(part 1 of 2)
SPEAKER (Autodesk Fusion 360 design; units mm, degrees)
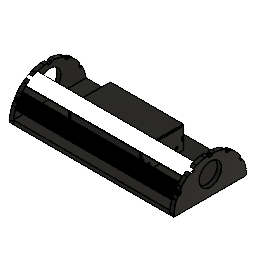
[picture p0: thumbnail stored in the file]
parameter "thickness" = 4
parameter "tabdepth" = 4
sketch "Sketch1" plane through (0, 0, 0) normal (0, 0, 1) x axis (1, 0, 0)
  line L1 (150, 0) -> (0, 0)
  line L2 (150, -70) -> (150, 0)
  line L3 (0, -70) -> (150, -70)
  line L4 (0, 0) -> (0, -70)
  point P1 (0, 0)
  point P2 (0, 0)
  point P3 (150, 0)
  point P5 (0, -70)
  horizontal L1
  vertical L2
  horizontal L3
  vertical L4
  coincident P1 P2
  dimension "d1" distance P2 P3 = 150
  dimension "d2" distance P2 P5 = 70
extrude "Extrude1" new body sketch "Sketch1" along normal blind 4
sketch "Sketch2" plane through (0, 0, 0) normal (-1, 0, 0) x axis (0, -1, 0)
  line L1 (70, 0) -> (0, 0)
  line L2 (70, 4) -> (70, 0)
  line L3 (0, 4) -> (70, 4)
  line L4 (0, 0) -> (0, 4)
  line L5 (60, 4) -> (10, 4)
  line L6 (60, 0) -> (60, 4)
  line L7 (10, 0) -> (60, 0)
  line L8 (10, 4) -> (10, 0)
  point P8 (60, 0)
  point P6 (10, 4)
  horizontal L5
  vertical L6
  horizontal L7
  vertical L8
  coincident L1 P8
  coincident L3 P6
  dimension "d7" distance L4 L8 = 10
  dimension "d8" distance L2 L6 = 10
extrude "Extrude2" add sketch "Sketch2" profile of L1 L3 L5 L6 L7 L8 along normal blind 4 (= "thickness")
sketch "Sketch3" plane through (150, 0, 0) normal (1, 0, 0) x axis (0, 1, 0)
  line L1 (0, 0) -> (-70, 0)
  line L2 (0, 4) -> (0, 0)
  line L3 (-70, 4) -> (0, 4)
  line L4 (-70, 0) -> (-70, 4)
  line L5 (-10, 4) -> (-60, 4)
  line L6 (-10, 0) -> (-10, 4)
  line L7 (-60, 0) -> (-10, 0)
  line L8 (-60, 4) -> (-60, 0)
  point P8 (-10, 0)
  point P10 (-10, 0)
  point P6 (-60, 4)
  horizontal L5
  vertical L6
  horizontal L7
  vertical L8
  coincident P8 P10
  coincident L3 P6
  dimension "d11" distance L4 L8 = 10
  dimension "d12" distance L2 L6 = 10
extrude "Extrude3" add sketch "Sketch3" profile of L1 L3 L5 L6 L7 L8 along normal blind 4 (= "thickness")
sketch "Sketch4" plane through (154, 0, 0) normal (1, 0, 0) x axis (0, 1, 0)
  line L1 (-10, 0) -> (-60, 0)
  line L2 (-10, 4) -> (-10, 0)
  line L3 (-60, 4) -> (-10, 4)
  line L4 (-60, 0) -> (-60, 4)
  line L5 (-70, 4) -> (-70, 0)
  line L6 (0, 0) -> (-70, 0)
  arc A1 centre (-35, 0) radius 35 clockwise from (-70, 0) to (0, 0)
  point P1 (0, 0)
  point P7 (0, 0)
  tangent A1 L5
  coincident P1 P7
  perpendicular L5 L6
extrude "Extrude4" new body sketch "Sketch4" profile of L2 L3 L4 A1 L6 no distance stored
extrude "Extrude5" of existing geometry no distance stored
sketch "Sketch5" plane through (150, 0, 0) normal (-1, 0, 0) x axis (0, -1, 0)
  line L1 (10, 0) -> (0, 0)
  line L2 (10, 4) -> (10, 0)
  line L3 (60, 4) -> (10, 4)
  line L4 (60, 0) -> (60, 4)
  line L5 (70, 0) -> (60, 0)
  arc A1 centre (35, 0) radius 35 clockwise from (0, 0) to (70, 0)
sketch "Sketch6" plane through (0, 0, 4) normal (0, 0, -1) x axis (1, 0, 0)
  line L1 (154, 60) -> (154, 10)
  line L2 (150, 60) -> (154, 60)
  line L3 (150, 10) -> (150, 60)
  line L4 (154, 10) -> (150, 10)
sketch "Sketch7" plane through (154, 0, 0) normal (1, 0, 0) x axis (0, 1, 0)
  line L1 (0, 0) -> (-10, 0)
  line L2 (-60, 0) -> (-70, 0)
  line L3 (-60, 4) -> (-60, 0)
  line L4 (-10, 4) -> (-60, 4)
  line L5 (-10, 0) -> (-10, 4)
  line L6 (-59.0789, 25.4009) -> (-63.6687, 20.0775)
  line L7 (-60.2396, 16.6833) -> (-63.6687, 20.0775)
  line L8 (-55.9565, 21.0105) -> (-60.2396, 16.6833)
  line L9 (-59.0789, 25.4009) -> (-55.9565, 21.0105)
  arc A1 centre (-35, 0) radius 35 clockwise from (-70, 0) to (0, 0)
  point P9 (-63.6687, 20.0775)
  point P10 (-59.0789, 25.4009)
  coincident A1 P9
  coincident A1 P10
  perpendicular L7 L8
sketch "Sketch9" plane through (154, 0, 0) normal (1, 0, 0) x axis (0, 1, 0)
  line L1 (0, 0) -> (-10, 0)
  line L2 (-60, 0) -> (-70, 0)
  line L3 (-60, 4) -> (-60, 0)
  line L4 (-10, 4) -> (-60, 4)
  line L5 (-10, 0) -> (-10, 4)
  line L6 (5.4969, 0) -> (-35, 0)
  line L7 (7.9535, 0) -> (-35, 0)
  line L8 (12.4131, 0) -> (-35, 0)
  horizontal L6
  horizontal L7
  horizontal L8
work_plane "WorkPlane3" AlongDistance -17.5
sketch "Sketch12" plane through (75, -35, 17.5) normal (0, 0, -1) x axis (1, 0, 0)
work_plane "WorkPlane4" AlongDistance -17.5
sketch "Sketch13" plane through (75, -35, 17.5) normal (0, 0, -1) x axis (1, 0, 0)
  line L1 (79, -35.0714) -> (79, 0)
  line L2 (75, -30.3109) -> (79, -30.3109)
  arc A1 centre (75, 0) radius 35 between (75, 35) and (75, -35)
  point P7 (79, -30.3109)
  point P8 (75, -30.3109)
  coincident L1 P7
  coincident A1 P8
work_plane "WorkPlane5" RotateAngle 60
sketch "Sketch27" plane through (154, 0, 0) normal (1, 0, 0) x axis (0, 1, 0)
  line L1 (0, 0) -> (-10, 0)
  line L2 (-60, 0) -> (-70, 0)
  line L3 (-60, 4) -> (-60, 0)
  line L4 (-10, 4) -> (-60, 4)
  line L5 (-10, 0) -> (-10, 4)
  arc A1 centre (-35, 0) radius 35 clockwise from (-70, 0) to (0, 0)
sketch "Sketch14" plane through (152, -4.6891, 17.5) normal (0, 0.866, 0.5) x axis (-1, 0, 0)
  line L1 (-2, 5) -> (-2, 0)
  line L2 (2, 5) -> (-2, 5)
  line L3 (2, -5) -> (2, 5)
  line L4 (-2, -5) -> (2, -5)
  line L5 (-2, 0) -> (-2, -5)
  point P2 (-2, 0)
  point P3 (-2, 0)
  point P4 (-2, 5)
  coincident P2 P3
  perpendicular L1 L2
  perpendicular L2 L3
  perpendicular L1 L4
  perpendicular L4 L5
  dimension "d34" distance P3 P4 = 5
extrude "Extrude8" cut sketch "Sketch14" against normal blind 4
sketch "Sketch15" plane through (75, -35, 17.5) normal (0, 0, -1) x axis (1, 0, 0)
  line L1 (79, 41.0609) -> (79, 0)
  line L2 (75, 30.3109) -> (79, 30.3109)
  arc A1 centre (79, 0) radius 35 between (79, -27.5) and (79, 35)
  point P7 (79, 30.3109)
  coincident A1 P7
  coincident L1 P7
work_plane "WorkPlane6" RotateAngle -60
sketch "Sketch16" plane through (152, -65.3109, 17.5) normal (0, -0.866, 0.5) x axis (-1, 0, 0)
  line L1 (2, -5) -> (2, 0)
  line L2 (-2, -5) -> (2, -5)
  line L3 (-2, 5) -> (-2, -5)
  line L4 (2, 5) -> (-2, 5)
  line L5 (2, 0) -> (2, 5)
  point P2 (2, 0)
  point P3 (2, 0)
  point P4 (2, -5)
  point P5 (-2, -5)
  point P6 (-2, 5)
  coincident P2 P3
  perpendicular L1 L2
  perpendicular L2 L3
  perpendicular L3 L4
  perpendicular L4 L5
  dimension "d39" distance P3 P4 = 5
  dimension "d40" distance P5 P6 = 10
extrude "Extrude9" cut sketch "Sketch16" against normal blind 4
work_plane "WorkPlane7" RotateAngle 0
sketch "Sketch17" plane through (152.9927, -35, 35) normal (0, 0, 1) x axis (1, 0, 0)
  line L1 (-3, 5) -> (-3, 0)
  line L2 (1, 5) -> (-3, 5)
  line L3 (1, -5) -> (1, 5)
  line L4 (-3, -5) -> (1, -5)
  line L5 (-3, 0) -> (-3, -5)
  vertical L1
  perpendicular L1 L2
  perpendicular L2 L3
  perpendicular L1 L4
  perpendicular L4 L5
extrude "Extrude10" cut sketch "Sketch17" against normal blind 4
work_plane "WorkPlane8" RotateAngle -7.5
sketch "Sketch18" plane through (150.7134, -52.7673, 30.155) normal (0, -0.5076, 0.8616) x axis (0, -0.8616, -0.5076)
  line L1 (-5, -0.75) -> (0, -0.75)
  line L2 (-5, 3.3553) -> (-5, -0.75)
  line L3 (5, 3.3553) -> (-5, 3.3553)
  line L4 (5, -0.75) -> (5, 3.3553)
  line L5 (0, -0.75) -> (5, -0.75)
  horizontal L1
  perpendicular L1 L2
  perpendicular L2 L3
  perpendicular L3 L4
  perpendicular L4 L5
extrude "Extrude11" cut sketch "Sketch18" against normal blind 4
extrude "Extrude12" cut of existing geometry blind -4
work_plane "WorkPlane9" RotateAngle 2.5
sketch "Sketch19" plane through (152.2402, -17.9965, 30.5922) normal (0, 0.4858, 0.8741) x axis (0, -0.8741, 0.4858)
  line L1 (5, 1.8) -> (0, 1.8)
  line L2 (5, -2.3) -> (5, 1.8)
  line L3 (-5, -2.3) -> (5, -2.3)
  line L4 (-5, 1.8) -> (-5, -2.3)
  line L5 (0, 1.8) -> (-5, 1.8)
  horizontal L1
  perpendicular L1 L2
  perpendicular L2 L3
  perpendicular L3 L4
  perpendicular L4 L5
extrude "Extrude13" cut sketch "Sketch19" against normal blind 4
sketch "Sketch20" plane through (154, 0, 0) normal (1, 0, 0) x axis (0, 1, 0)
  line L1 (-22.5412, 32.7075) -> (-24.31, 29.525)
  line L2 (-30, 31) -> (-30, 34.641)
  line L3 (-40, 31) -> (-30, 31)
  line L4 (-40, 34.641) -> (-40, 31)
  line L5 (-46.4289, 29.2469) -> (-48.2772, 32.3839)
  line L6 (-55.0446, 24.1705) -> (-46.4289, 29.2469)
  line L7 (-56.8929, 27.3075) -> (-55.0446, 24.1705)
  line L8 (-59.3468, 19.8301) -> (-62.5, 21.6506)
  line L9 (-64.3468, 11.1699) -> (-59.3468, 19.8301)
  line L10 (-67.5, 12.9904) -> (-64.3468, 11.1699)
  line L11 (-60, 0) -> (-70, 0)
  line L12 (-60, 4) -> (-60, 0)
  line L13 (-10, 4) -> (-60, 4)
  line L14 (-10, 0) -> (-10, 4)
  line L15 (0, 0) -> (-10, 0)
  line L16 (-5.6532, 11.1699) -> (-2.5, 12.9904)
  line L17 (-10.6532, 19.8301) -> (-5.6532, 11.1699)
  line L18 (-7.5, 21.6506) -> (-10.6532, 19.8301)
  line L19 (-15.5694, 24.6668) -> (-13.8006, 27.8493)
  line L20 (-24.31, 29.525) -> (-15.5694, 24.6668)
  arc A1 centre (-35, 0) radius 35 clockwise from (-30, 34.641) to (-22.5412, 32.7075)
  arc A2 centre (-35, 0) radius 35 clockwise from (-48.2772, 32.3839) to (-40, 34.641)
  arc A3 centre (-35, 0) radius 35 clockwise from (-62.5, 21.6506) to (-56.8929, 27.3075)
  arc A4 centre (-35, 0) radius 35 clockwise from (-70, 0) to (-67.5, 12.9904)
  arc A5 centre (-35, 0) radius 35 clockwise from (-2.5, 12.9904) to (0, 0)
  arc A6 centre (-35, 0) radius 35 clockwise from (-13.8006, 27.8493) to (-7.5, 21.6506)
sketch "Sketch21" plane through (154, 0, 0) normal (1, 0, 0) x axis (0, 1, 0)
  line L1 (-22.5412, 32.7075) -> (-24.31, 29.525)
  line L2 (-30, 31) -> (-30, 34.641)
  line L3 (-40, 31) -> (-30, 31)
  line L4 (-40, 34.641) -> (-40, 31)
  line L5 (-46.4289, 29.2469) -> (-48.2772, 32.3839)
  line L6 (-55.0446, 24.1705) -> (-46.4289, 29.2469)
  line L7 (-56.8929, 27.3075) -> (-55.0446, 24.1705)
  line L8 (-59.3468, 19.8301) -> (-62.5, 21.6506)
  line L9 (-64.3468, 11.1699) -> (-59.3468, 19.8301)
  line L10 (-67.5, 12.9904) -> (-64.3468, 11.1699)
  line L11 (-60, 0) -> (-70, 0)
  line L12 (-60, 4) -> (-60, 0)
  line L13 (-10, 4) -> (-60, 4)
  line L14 (-10, 0) -> (-10, 4)
  line L15 (0, 0) -> (-10, 0)
  line L16 (-5.6532, 11.1699) -> (-2.5, 12.9904)
  line L17 (-10.6532, 19.8301) -> (-5.6532, 11.1699)
  line L18 (-7.5, 21.6506) -> (-10.6532, 19.8301)
  line L19 (-15.5694, 24.6668) -> (-13.8006, 27.8493)
  line L20 (-24.31, 29.525) -> (-15.5694, 24.6668)
  arc A1 centre (-35, 0) radius 35 clockwise from (-30, 34.641) to (-22.5412, 32.7075)
  arc A2 centre (-35, 0) radius 35 clockwise from (-48.2772, 32.3839) to (-40, 34.641)
  arc A3 centre (-35, 0) radius 35 clockwise from (-62.5, 21.6506) to (-56.8929, 27.3075)
  arc A4 centre (-35, 0) radius 35 clockwise from (-70, 0) to (-67.5, 12.9904)
  arc A5 centre (-35, 0) radius 35 clockwise from (-2.5, 12.9904) to (0, 0)
  arc A6 centre (-35, 0) radius 35 clockwise from (-13.8006, 27.8493) to (-7.5, 21.6506)
sketch "Sketch22" plane through (154, 0, 0) normal (1, 0, 0) x axis (0, 1, 0)
  line L1 (-22.5412, 32.7075) -> (-24.31, 29.525)
  line L2 (-30, 31) -> (-30, 34.641)
  line L3 (-40, 31) -> (-30, 31)
  line L4 (-40, 34.641) -> (-40, 31)
  line L5 (-46.4289, 29.2469) -> (-48.2772, 32.3839)
  line L6 (-55.0446, 24.1705) -> (-46.4289, 29.2469)
  line L7 (-56.8929, 27.3075) -> (-55.0446, 24.1705)
  line L8 (-59.3468, 19.8301) -> (-62.5, 21.6506)
  line L9 (-64.3468, 11.1699) -> (-59.3468, 19.8301)
  line L10 (-67.5, 12.9904) -> (-64.3468, 11.1699)
  line L11 (-60, 0) -> (-70, 0)
  line L12 (-60, 4) -> (-60, 0)
  line L13 (-10, 4) -> (-60, 4)
  line L14 (-10, 0) -> (-10, 4)
  line L15 (0, 0) -> (-10, 0)
  line L16 (-5.6532, 11.1699) -> (-2.5, 12.9904)
  line L17 (-10.6532, 19.8301) -> (-5.6532, 11.1699)
  line L18 (-7.5, 21.6506) -> (-10.6532, 19.8301)
  line L19 (-15.5694, 24.6668) -> (-13.8006, 27.8493)
  line L20 (-24.31, 29.525) -> (-15.5694, 24.6668)
  arc A1 centre (-35, 0) radius 35 clockwise from (-30, 34.641) to (-22.5412, 32.7075)
  arc A2 centre (-35, 0) radius 35 clockwise from (-48.2772, 32.3839) to (-40, 34.641)
  arc A3 centre (-35, 0) radius 35 clockwise from (-62.5, 21.6506) to (-56.8929, 27.3075)
  arc A4 centre (-35, 0) radius 35 clockwise from (-70, 0) to (-67.5, 12.9904)
  arc A5 centre (-35, 0) radius 35 clockwise from (-2.5, 12.9904) to (0, 0)
  arc A6 centre (-35, 0) radius 35 clockwise from (-13.8006, 27.8493) to (-7.5, 21.6506)
scale "Scale1" ScaleFactor "2 pcs"
sketch "Sketch23" plane through (308, 0, 0) normal (1, 0, 0) x axis (0, 1, 0)
  line L1 (24.9177, 61.4149) -> (21.3799, 55.05)
  line L2 (10, 58) -> (10, 65.282)
  line L3 (-10, 58) -> (10, 58)
  line L4 (-10, 65.282) -> (-10, 58)
  line L5 (-22.8577, 54.4938) -> (-26.5544, 60.7678)
  line L6 (-40.0892, 44.3411) -> (-22.8577, 54.4938)
  line L7 (-43.7858, 50.615) -> (-40.0892, 44.3411)
  line L8 (-48.6936, 35.6603) -> (-55, 39.3013)
  line L9 (-58.6936, 18.3397) -> (-48.6936, 35.6603)
  line L10 (-65, 21.9808) -> (-58.6936, 18.3397)
  line L11 (-50, -4) -> (-70, -4)
  line L12 (-50, 4) -> (-50, -4)
  line L13 (50, 4) -> (-50, 4)
  line L14 (50, -4) -> (50, 4)
  line L15 (70, -4) -> (50, -4)
  line L16 (58.6936, 18.3397) -> (65, 21.9808)
  line L17 (48.6936, 35.6603) -> (58.6936, 18.3397)
  line L18 (55, 39.3013) -> (48.6936, 35.6603)
  line L19 (38.8612, 45.3337) -> (42.3989, 51.6986)
  line L20 (21.3799, 55.05) -> (38.8612, 45.3337)
  arc A1 centre (0, -4) radius 70 clockwise from (10, 65.282) to (24.9177, 61.4149)
  arc A2 centre (0, -4) radius 70 clockwise from (-26.5544, 60.7678) to (-10, 65.282)
  arc A3 centre (0, -4) radius 70 clockwise from (-55, 39.3013) to (-43.7858, 50.615)
  arc A4 centre (0, -4) radius 70 clockwise from (-70, -4) to (-65, 21.9808)
  arc A5 centre (0, -4) radius 70 clockwise from (65, 21.9808) to (70, -4)
  arc A6 centre (0, -4) radius 70 clockwise from (42.3989, 51.6986) to (55, 39.3013)
sketch "Sketch24" plane through (308, 0, 0) normal (1, 0, 0) x axis (0, 1, 0)
  line L1 (24.9177, 61.4149) -> (21.3799, 55.05)
  line L2 (10, 58) -> (10, 65.282)
  line L3 (-10, 58) -> (10, 58)
  line L4 (-10, 65.282) -> (-10, 58)
  line L5 (-22.8577, 54.4938) -> (-26.5544, 60.7678)
  line L6 (-40.0892, 44.3411) -> (-22.8577, 54.4938)
  line L7 (-43.7858, 50.615) -> (-40.0892, 44.3411)
  line L8 (-48.6936, 35.6603) -> (-55, 39.3013)
  line L9 (-58.6936, 18.3397) -> (-48.6936, 35.6603)
  line L10 (-65, 21.9808) -> (-58.6936, 18.3397)
  line L11 (-50, -4) -> (-70, -4)
  line L12 (-50, 4) -> (-50, -4)
  line L13 (50, 4) -> (-50, 4)
  line L14 (50, -4) -> (50, 4)
  line L15 (70, -4) -> (50, -4)
  line L16 (58.6936, 18.3397) -> (65, 21.9808)
  line L17 (48.6936, 35.6603) -> (58.6936, 18.3397)
  line L18 (55, 39.3013) -> (48.6936, 35.6603)
  line L19 (38.8612, 45.3337) -> (42.3989, 51.6986)
  line L20 (21.3799, 55.05) -> (38.8612, 45.3337)
  arc A1 centre (0, -4) radius 70 clockwise from (10, 65.282) to (24.9177, 61.4149)
  arc A2 centre (0, -4) radius 70 clockwise from (-26.5544, 60.7678) to (-10, 65.282)
  arc A3 centre (0, -4) radius 70 clockwise from (-55, 39.3013) to (-43.7858, 50.615)
  arc A4 centre (0, -4) radius 70 clockwise from (-70, -4) to (-65, 21.9808)
  arc A5 centre (0, -4) radius 70 clockwise from (65, 21.9808) to (70, -4)
  arc A6 centre (0, -4) radius 70 clockwise from (42.3989, 51.6986) to (55, 39.3013)
sketch "Sketch25" plane through (0, 0, 0) normal (1, 0, 0) x axis (0, 1, 0)
  circle C1 centre (151.5757, 61.4467) radius 32.5
  dimension "d55" diameter C1 = 65
scale "Scale2" ScaleFactor "1.5 pcs"
sketch "Sketch26" plane through (312, 0, 0) normal (1, 0, 0) x axis (0, 1, 0)
  line L1 (12.3765, 90.1224) -> (7.0699, 80.5749)
  line L2 (-10, 85) -> (-10, 95.923)
  line L3 (-40, 85) -> (-10, 85)
  line L4 (-40, 95.923) -> (-40, 85)
  line L5 (-59.2866, 79.7407) -> (-64.8316, 89.1517)
  line L6 (-85.1338, 64.5116) -> (-59.2866, 79.7407)
  line L7 (-90.6787, 73.9226) -> (-85.1338, 64.5116)
  line L8 (-98.0404, 51.4904) -> (-107.5, 56.9519)
  line L9 (-113.0404, 25.5096) -> (-98.0404, 51.4904)
  line L10 (-122.5, 30.9711) -> (-113.0404, 25.5096)
  line L11 (-100, -8) -> (-130, -8)
  line L12 (-100, 4) -> (-100, -8)
  line L13 (50, 4) -> (-100, 4)
  line L14 (50, -8) -> (50, 4)
  line L15 (80, -8) -> (50, -8)
  line L16 (63.0404, 25.5096) -> (72.5, 30.9711)
  line L17 (48.0404, 51.4904) -> (63.0404, 25.5096)
  line L18 (57.5, 56.9519) -> (48.0404, 51.4904)
  line L19 (33.2917, 66.0005) -> (38.5983, 75.5479)
  line L20 (7.0699, 80.5749) -> (33.2917, 66.0005)
  arc A1 centre (-25, -8) radius 105 clockwise from (-10, 95.923) to (12.3765, 90.1224)
  arc A2 centre (-25, -8) radius 105 clockwise from (-64.8316, 89.1517) to (-40, 95.923)
  arc A3 centre (-25, -8) radius 105 clockwise from (-107.5, 56.9519) to (-90.6787, 73.9226)
  arc A4 centre (-25, -8) radius 105 clockwise from (-130, -8) to (-122.5, 30.9711)
  arc A5 centre (-25, -8) radius 105 clockwise from (72.5, 30.9711) to (80, -8)
  arc A6 centre (-25, -8) radius 105 clockwise from (38.5983, 75.5479) to (57.5, 56.9519)
  circle C1 centre (-24.0478, 41.1529) radius 32.5
  dimension "d57" diameter C1 = 65
extrude "Extrude14" add of existing geometry blind 10
sketch "Sketch28" plane through (0, -34.9801, -20.6102) normal (0, 0.8616, 0.5076) x axis (-1, 0, 0)
  line L1 (-300, 109.7214) -> (-300, 98.7983)
  line L2 (-312, 109.7214) -> (-300, 109.7214)
  line L3 (-312, 98.7983) -> (-312, 109.7214)
  line L4 (-300, 98.7983) -> (-312, 98.7983)
extrude "Extrude15" add of existing geometry blind 10
extrude "Extrude16" add of existing geometry blind 10
extrude "Extrude17" add of existing geometry blind 10
extrude "Extrude18" add of existing geometry blind 10
extrude "Extrude19" add of existing geometry blind 10
extrude "Extrude20" add of existing geometry blind 10
extrude "Extrude21" add of existing geometry blind 10
extrude "Extrude22" add of existing geometry blind 10
extrude "Extrude23" add of existing geometry blind 10
sketch "Sketch29" plane through (0, 0, 95.923) normal (0, 0, 1) x axis (-1, 0, 0)
  line L1 (-300, 10) -> (-312, 10)
  line L2 (-300, 20) -> (-300, 10)
  line L3 (-312, 20) -> (-300, 20)
  line L4 (-312, 10) -> (-312, 20)
sketch "Sketch30" plane through (0, 0, 95.923) normal (0, 0, 1) x axis (-1, 0, 0)
  line L1 (-312, 40) -> (-300, 40)
  line L2 (-312, 30) -> (-312, 40)
  line L3 (-300, 30) -> (-312, 30)
  line L4 (-300, 40) -> (-300, 30)
extrude "Extrude24" add of existing geometry blind 6.923
extrude "Extrude25" add of existing geometry blind 6.923
extrude "Extrude26" add of existing geometry blind 6.923
extrude "Extrude27" add of existing geometry blind 6.923
extrude "Extrude28" add of existing geometry blind 6.923
sketch "Sketch31" plane through (312, 0, 0) normal (1, 0, 0) x axis (0, 1, 0)
  line L1 (-20, 95.923) -> (-10, 95.923)
  line L2 (-20, 91.923) -> (-20, 95.923)
  line L3 (-30, 91.923) -> (-20, 91.923)
  line L4 (-30, 95.923) -> (-30, 91.923)
  line L5 (-40, 95.923) -> (-30, 95.923)
  line L6 (-73.4473, 84.0753) -> (-64.8316, 89.1517)
  line L7 (-71.4167, 80.629) -> (-73.4473, 84.0753)
  line L8 (-80.0324, 75.5526) -> (-71.4167, 80.629)
  line L9 (-82.063, 78.9989) -> (-80.0324, 75.5526)
  line L10 (-90.6787, 73.9226) -> (-82.063, 78.9989)
  line L11 (-112.5, 48.2917) -> (-107.5, 56.9519)
  line L12 (-109.0359, 46.2916) -> (-112.5, 48.2917)
  line L13 (-114.0359, 37.6314) -> (-109.0359, 46.2916)
  line L14 (-117.5, 39.6314) -> (-114.0359, 37.6314)
  line L15 (-122.5, 30.9711) -> (-117.5, 39.6314)
  line L16 (-100, -8) -> (-130, -8)
  line L17 (-100, 4) -> (-100, -8)
  line L18 (50, 4) -> (-100, 4)
  line L19 (50, -8) -> (50, 4)
  line L20 (80, -8) -> (50, -8)
  line L21 (67.5, 39.6314) -> (72.5, 30.9711)
  line L22 (64.0359, 37.6314) -> (67.5, 39.6314)
  line L23 (59.0359, 46.2916) -> (64.0359, 37.6314)
  line L24 (62.5, 48.2917) -> (59.0359, 46.2916)
  line L25 (57.5, 56.9519) -> (62.5, 48.2917)
  line L26 (29.8577, 80.4061) -> (38.5983, 75.5479)
  line L27 (27.9144, 76.9098) -> (29.8577, 80.4061)
  line L28 (19.1738, 81.7679) -> (27.9144, 76.9098)
  line L29 (21.1171, 85.2642) -> (19.1738, 81.7679)
  line L30 (12.3765, 90.1224) -> (21.1171, 85.2642)
  arc A1 centre (-25, -8) radius 105 clockwise from (-10, 95.923) to (12.3765, 90.1224)
  arc A2 centre (-25, -8) radius 105 clockwise from (-64.8316, 89.1517) to (-40, 95.923)
  arc A3 centre (-25, -8) radius 105 clockwise from (-107.5, 56.9519) to (-90.6787, 73.9226)
  arc A4 centre (-25, -8) radius 105 clockwise from (-130, -8) to (-122.5, 30.9711)
  arc A5 centre (-25, -8) radius 105 clockwise from (72.5, 30.9711) to (80, -8)
  arc A6 centre (-25, -8) radius 105 clockwise from (38.5983, 75.5479) to (57.5, 56.9519)
  circle C1 centre (-25, 48) radius 32.25
  dimension "d88" diameter C1 = 64.5
extrude "Extrude29" cut of existing geometry blind -0.025
extrude "Extrude30" cut of existing geometry blind -0.025
extrude "Extrude31" cut of existing geometry blind -7
extrude "Extrude32" cut of existing geometry blind -0.05
extrude "Extrude33" cut of existing geometry blind -0.05
extrude "Extrude34" add of existing geometry blind 0.1
extrude "Extrude35" add of existing geometry blind 0.1
extrude "Extrude36" cut of existing geometry blind -1
extrude "Extrude37" cut of existing geometry blind -1
extrude "Extrude38" cut of existing geometry blind -1
extrude "Extrude39" cut of existing geometry blind -1
extrude "Extrude40" cut of existing geometry blind -1
extrude "Extrude41" add of existing geometry blind 0.05
extrude "Extrude42" add of existing geometry blind 0.05
extrude "Extrude43" cut of existing geometry blind -0.025
extrude "Extrude44" cut of existing geometry blind -0.025
extrude "Extrude45" add of existing geometry blind 0.025
extrude "Extrude46" add of existing geometry blind 0.025
extrude "Extrude47" add of existing geometry blind 0.025
extrude "Extrude48" add of existing geometry blind 0.025
extrude "Extrude49" add of existing geometry blind 0.025
extrude "Extrude50" add of existing geometry blind 0.025
extrude "Extrude51" add of existing geometry blind 0.025
extrude "Extrude52" add of existing geometry blind 0.025
sketch "Sketch32" plane through (312, 0, 0) normal (1, 0, 0) x axis (0, 1, 0)
  line L1 (-108.1823, 45.77) -> (-112.5125, 48.27)
  line L2 (-113.1573, 37.153) -> (-108.1823, 45.77)
  line L3 (-117.4875, 39.653) -> (-113.1573, 37.153)
  line L4 (-122.5, 30.9711) -> (-117.4875, 39.653)
  line L5 (-99.975, -1) -> (-129.7664, -1)
  line L6 (-99.975, 4) -> (-99.975, -1)
  line L7 (49.975, 4) -> (-99.975, 4)
  line L8 (49.975, -1) -> (49.975, 4)
  line L9 (79.7664, -1) -> (49.975, -1)
  line L10 (67.4875, 39.653) -> (72.5, 30.9711)
  line L11 (63.1573, 37.153) -> (67.4875, 39.653)
  line L12 (58.1823, 45.77) -> (63.1573, 37.153)
  line L13 (62.5125, 48.27) -> (58.1823, 45.77)
  line L14 (57.5, 56.9519) -> (62.5125, 48.27)
  line L15 (29.8359, 80.4182) -> (38.5983, 75.5479)
  line L16 (27.4068, 76.0479) -> (29.8359, 80.4182)
  line L17 (18.7099, 80.8817) -> (27.4068, 76.0479)
  line L18 (21.139, 85.2521) -> (18.7099, 80.8817)
  line L19 (12.3765, 90.1224) -> (21.139, 85.2521)
  line L20 (-20.025, 95.923) -> (-10, 95.923)
  line L21 (-20.025, 90.923) -> (-20.025, 95.923)
  line L22 (-29.975, 90.923) -> (-20.025, 90.923)
  line L23 (-29.975, 95.923) -> (-29.975, 90.923)
  line L24 (-40, 95.923) -> (-29.975, 95.923)
  line L25 (-73.4688, 84.0626) -> (-64.8316, 89.1517)
  line L26 (-70.9306, 79.7547) -> (-73.4688, 84.0626)
  line L27 (-79.5032, 74.7037) -> (-70.9306, 79.7547)
  line L28 (-82.0415, 79.0116) -> (-79.5032, 74.7037)
  line L29 (-90.6787, 73.9226) -> (-82.0415, 79.0116)
  line L30 (-112.5125, 48.27) -> (-107.5, 56.9519)
  arc A1 centre (-25, -8) radius 105 clockwise from (-129.7664, -1) to (-122.5, 30.9711)
  arc A2 centre (-25, -8) radius 105 clockwise from (72.5, 30.9711) to (79.7664, -1)
  arc A3 centre (-25, -8) radius 105 clockwise from (38.5983, 75.5479) to (57.5, 56.9519)
  arc A4 centre (-25, -8) radius 105 clockwise from (-10, 95.923) to (12.3765, 90.1224)
  arc A5 centre (-25, -8) radius 105 clockwise from (-64.8316, 89.1517) to (-40, 95.923)
  arc A6 centre (-25, -8) radius 105 clockwise from (-107.5, 56.9519) to (-90.6787, 73.9226)
  circle C1 centre (-25, 47.4615) radius 32.25
  dimension "d138" diameter C1 = 64.5
extrude "Extrude53" add of existing geometry blind 0.025
extrude "Extrude54" add of existing geometry blind 0.025
extrude "Extrude55" add of existing geometry blind 0.025
extrude "Extrude56" add of existing geometry blind 0.025
extrude "Extrude57" add of existing geometry blind 0.025
extrude "Extrude58" add of existing geometry blind 0.025
extrude "Extrude59" add of existing geometry blind 0.025
extrude "Extrude60" add of existing geometry blind 0.025
extrude "Extrude61" add of existing geometry blind 0.025
extrude "Extrude62" add of existing geometry blind 0.025
sketch "Sketch33" plane through (312, 0, 0) normal (1, 0, 0) x axis (0, 1, 0)
  line L1 (-113.1448, 37.1747) -> (-108.1948, 45.7483)
  line L2 (-117.475, 39.6747) -> (-113.1448, 37.1747)
  line L3 (-122.5, 30.9711) -> (-117.475, 39.6747)
  line L4 (-99.975, -1) -> (-129.7664, -1)
  line L5 (-99.975, 4) -> (-99.975, -1)
  line L6 (49.975, 4) -> (-99.975, 4)
  line L7 (49.975, -1) -> (49.975, 4)
  line L8 (79.7664, -1) -> (49.975, -1)
  line L9 (67.475, 39.6747) -> (72.5, 30.9711)
  line L10 (63.1448, 37.1747) -> (67.475, 39.6747)
  line L11 (58.1948, 45.7483) -> (63.1448, 37.1747)
  line L12 (62.525, 48.2483) -> (58.1948, 45.7483)
  line L13 (57.5, 56.9519) -> (62.525, 48.2483)
  line L14 (29.814, 80.4303) -> (38.5983, 75.5479)
  line L15 (27.3849, 76.06) -> (29.814, 80.4303)
  line L16 (18.7317, 80.8696) -> (27.3849, 76.06)
  line L17 (21.1608, 85.2399) -> (18.7317, 80.8696)
  line L18 (12.3765, 90.1224) -> (21.1608, 85.2399)
  line L19 (-20.05, 95.923) -> (-10, 95.923)
  line L20 (-20.05, 90.923) -> (-20.05, 95.923)
  line L21 (-29.95, 90.923) -> (-20.05, 90.923)
  line L22 (-29.95, 95.923) -> (-29.95, 90.923)
  line L23 (-40, 95.923) -> (-29.95, 95.923)
  line L24 (-73.4904, 84.0499) -> (-64.8316, 89.1517)
  line L25 (-70.9521, 79.742) -> (-73.4904, 84.0499)
  line L26 (-79.4817, 74.7164) -> (-70.9521, 79.742)
  line L27 (-82.0199, 79.0243) -> (-79.4817, 74.7164)
  line L28 (-90.6787, 73.9226) -> (-82.0199, 79.0243)
  line L29 (-112.525, 48.2483) -> (-107.5, 56.9519)
  line L30 (-108.1948, 45.7483) -> (-112.525, 48.2483)
  arc A1 centre (-25, -8) radius 105 clockwise from (-129.7664, -1) to (-122.5, 30.9711)
  arc A2 centre (-25, -8) radius 105 clockwise from (72.5, 30.9711) to (79.7664, -1)
  arc A3 centre (-25, -8) radius 105 clockwise from (38.5983, 75.5479) to (57.5, 56.9519)
  arc A4 centre (-25, -8) radius 105 clockwise from (-10, 95.923) to (12.3765, 90.1224)
  arc A5 centre (-25, -8) radius 105 clockwise from (-64.8316, 89.1517) to (-40, 95.923)
  arc A6 centre (-25, -8) radius 105 clockwise from (-107.5, 56.9519) to (-90.6787, 73.9226)
  circle C1 centre (-25, 47.4615) radius 32
  dimension "d161" diameter C1 = 64
extrude "Extrude63" add of existing geometry blind 10
extrude "Extrude64" add of existing geometry blind 10
extrude "Extrude65" cut sketch "Sketch33" profile of C1 against normal blind 60
work_plane "WorkPlane10" AlongDistance 0
split "Split1"
extrude "Extrude66" cut of existing geometry blind -3
extrude "Extrude67" cut of existing geometry blind -3
work_plane "WorkPlane11" AlongDistance 0
split "Split2"
copy_paste_bodies "CopyPasteBodies1"
move "Move1"
align "Align1"
sketch "Sketch34" plane through (0, 0, 0) normal (0, 1, 0) x axis (1, 0, 0)
sketch "Sketch35" plane through (0, 0, 4) normal (0, 0, 1) x axis (-1, 0, 0)
  line L1 (-300, -80) -> (-300, 130)
  line L2 (150, -80) -> (-300, -80)
  line L3 (150, 130) -> (150, -80)
  line L4 (-300, 130) -> (150, 130)
  line L5 (-300, -250) -> (150, -250)
  line L6 (-300, -212) -> (-300, -250)
  line L7 (150, -212) -> (-300, -212)
  line L8 (150, -250) -> (150, -212)
  point P6 (150, -250)
  point P7 (-300, -250)
  point P9 (150, -212)
  horizontal L5
  vertical L6
  horizontal L7
  vertical L8
  dimension "d174" distance P6 P7 = 450
  dimension "d175" distance P6 P9 = 38
extrude "Extrude68" new body sketch "Sketch35" profile of L5 L6 L7 L8 along normal blind 5
sketch "Sketch36" plane through (-150, 0, 0) normal (-1, 0, 0) x axis (0, -1, 0)
  line L1 (-212, 4) -> (-250, 4)
  line L2 (-212, 9) -> (-212, 4)
  line L3 (-250, 9) -> (-212, 9)
  line L4 (-250, 4) -> (-250, 9)
  line L5 (-235.95, 4) -> (-226.05, 4)
  line L6 (-235.95, 9) -> (-235.95, 4)
  line L7 (-226.05, 9) -> (-235.95, 9)
  line L8 (-226.05, 4) -> (-226.05, 9)
  line L9 (-235.95, 9) -> (-226.05, 4)
  line L10 (-226.05, 9) -> (-235.95, 4)
  point P10 (-231, 6.5)
  point P8 (-235.95, 9)
  point P9 (-226.05, 9)
  point P7 (-235.95, 4)
  perpendicular L5 L6
  parallel L5 L7
  parallel L6 L8
  horizontal L5
  coincident L9 P10
  coincident L10 P10
  dimension "d178" distance P8 P9 = 9.9
  dimension "d179" distance P7 P8 = 5
extrude "Extrude69" add sketch "Sketch36" profile of L1 L3 L5 L6 L7 L8 along normal blind 5
extrude "Extrude70" add of existing geometry blind 7
sketch "Sketch37" plane through (300, 0, 0) normal (1, 0, 0) x axis (0, 1, 0)
  line L1 (250, 4) -> (212, 4)
  line L2 (250, 9) -> (250, 4)
  line L3 (212, 9) -> (250, 9)
  line L4 (212, 4) -> (212, 9)
  line L5 (226.05, 4) -> (235.95, 4)
  line L6 (226.05, 9) -> (226.05, 4)
  line L7 (235.95, 9) -> (226.05, 9)
  line L8 (235.95, 4) -> (235.95, 9)
  line L9 (226.05, 9) -> (235.95, 4)
  line L10 (235.95, 9) -> (226.05, 4)
  point P10 (231, 6.5)
  point P8 (226.05, 9)
  point P9 (235.95, 9)
  perpendicular L5 L6
  parallel L5 L7
  parallel L6 L8
  horizontal L5
  coincident L9 P10
  coincident L10 P10
  dimension "d184" distance P8 P9 = 9.9
extrude "Extrude71" add sketch "Sketch37" profile of L1 L3 L5 L6 L7 L8 along normal blind 12
align "Align2"
copy_paste_bodies "CopyPasteBodies2"
move "Move2"
copy_paste_bodies "CopyPasteBodies3"
move "Move3"
copy_paste_bodies "CopyPasteBodies4"
move "Move4"
copy_paste_bodies "CopyPasteBodies5"
move "Move5"
align "Align3"
align "Align4"
align "Align5"
align "Align6"
sketch "Sketch1" plane through (0, 0, 0) normal (0, 1, 0) x axis (1, 0, 0)
  line L1 (130, 0) -> (0, 0)
  line L2 (130, 120) -> (130, 0)
  line L3 (0, 120) -> (130, 120)
  line L4 (0, 0) -> (0, 120)
  line L5 (5, 0) -> (0, 0)
  line L6 (5, 5) -> (5, 0)
  line L7 (125, 5) -> (5, 5)
  line L8 (125, 115) -> (125, 5)
  line L9 (5, 115) -> (125, 115)
  line L10 (5, 5) -> (5, 115)
  point P1 (0, 0)
  point P2 (0, 0)
  point P6 (0, 0)
  point P3 (130, 0)
  point P5 (0, 120)
  point P7 (5, 0)
  point P8 (5, 5)
  point P11 (5, 115)
  point P9 (125, 5)
  horizontal L1
  vertical L2
  horizontal L3
  vertical L4
  coincident P1 P2
  coincident P1 P6
  parallel L1 L5
  perpendicular L1 L6
  horizontal L7
  vertical L8
  horizontal L9
  vertical L10
  dimension "d1_1" distance P2 P3 = 130
  dimension "d2_1" distance P2 P5 = 120
  dimension "d3_1" distance P6 P7 = 5
  dimension "d4_1" distance P7 P8 = 5
  dimension "d5" distance P8 P11 = 110
  dimension "d6" distance P8 P9 = 120
extrude "Extrude1" new body sketch "Sketch1" profile of L1 L2 L3 L4 L5 L7 L8 L9 L10 along normal blind 60 named "d7_1"
sketch "Sketch2" plane through (0, 0, 0) normal (-1, 0, 0) x axis (0, 0, 1)
  line L1 (0, 0) -> (-120, 0)
  line L2 (0, 60) -> (0, 0)
  line L3 (-120, 60) -> (0, 60)
  line L4 (-120, 0) -> (-120, 60)
  line L5 (-57.5, 17.5) -> (-62.5, 17.5)
  line L6 (-57.5, 12.5) -> (-57.5, 17.5)
  line L7 (-62.5, 12.5) -> (-57.5, 12.5)
  line L8 (-62.5, 17.5) -> (-62.5, 12.5)
  line L9 (-103.5, 12.5) -> (-97.5, 12.5)
  line L10 (-103.5, 17.5) -> (-103.5, 12.5)
  line L11 (-97.5, 17.5) -> (-103.5, 17.5)
  line L12 (-97.5, 12.5) -> (-97.5, 17.5)
  line L13 (-16.5, 12.5) -> (-22.5, 12.5)
  line L14 (-16.5, 17.5) -> (-16.5, 12.5)
  line L15 (-22.5, 17.5) -> (-16.5, 17.5)
  line L16 (-22.5, 12.5) -> (-22.5, 17.5)
  point P6 (-62.5, 17.5)
  point P7 (-57.5, 17.5)
  point P9 (-62.5, 12.5)
  point P10 (-97.5, 12.5)
  point P11 (-103.5, 12.5)
  point P13 (-97.5, 17.5)
  point P14 (-22.5, 12.5)
  point P15 (-16.5, 12.5)
  point P17 (-22.5, 17.5)
  horizontal L5
  vertical L6
  horizontal L7
  vertical L8
  horizontal L9
  vertical L10
  horizontal L11
  vertical L12
  horizontal L13
  vertical L14
  horizontal L15
  vertical L16
  dimension "d9_1" distance P6 P7 = 5
  dimension "d10_1" distance P6 P9 = 5
  dimension "d12_1" distance P10 P11 = 6
  dimension "d13_1" distance P10 P13 = 5
  dimension "d15_1" distance P14 P15 = 6
  dimension "d16_1" distance P14 P17 = 5
extrude "Extrude2" cut sketch "Sketch2" profile of L5 L6 L7 L8 L9 L10 L11 L12 L13 L14 L15 L16 against normal blind 25 named "d17_1"
sketch "Sketch3" plane through (0, 0, 0) normal (-1, 0, 0) x axis (0, 0, 1)
  line L1 (-103.5, 17.5) -> (-103.5, 12.5)
  line L2 (-97.5, 17.5) -> (-103.5, 17.5)
  line L3 (-97.5, 12.5) -> (-97.5, 17.5)
  line L4 (-103.5, 12.5) -> (-97.5, 12.5)
  line L5 (-57.5, 12.5) -> (-57.5, 17.5)
  line L6 (-62.5, 12.5) -> (-57.5, 12.5)
  line L7 (-62.5, 17.5) -> (-62.5, 12.5)
  line L8 (-57.5, 17.5) -> (-62.5, 17.5)
  line L9 (-22.5, 12.5) -> (-16.5, 12.5)
  line L10 (-22.5, 17.5) -> (-22.5, 12.5)
  line L11 (-16.5, 17.5) -> (-22.5, 17.5)
  line L12 (-16.5, 12.5) -> (-16.5, 17.5)
  line L13 (0, 0) -> (-120, 0)
  line L14 (0, 60) -> (0, 0)
  line L15 (-120, 60) -> (0, 60)
  line L16 (-120, 0) -> (-120, 60)
  line L17 (-97.5, 17.5) -> (-103.5, 17.5)
  line L18 (-97.5, 12.5) -> (-97.5, 17.5)
  line L19 (-103.5, 12.5) -> (-97.5, 12.5)
  line L20 (-103.5, 17.5) -> (-103.5, 12.5)
  point P5 (-97.5, 12.5)
  point P20 (-97.5, 12.5)
  point P3 (-103.5, 17.5)
  point P18 (-103.5, 17.5)
  horizontal L17
  vertical L18
  horizontal L19
  vertical L20
  coincident P5 P20
  coincident P3 P18
extrude "Extrude3" cut sketch "Sketch3" profile of L1 L2 L3 L4 L17 L18 L19 L20 against normal blind 135 named "d19_1"
extrude "Extrude4" cut of existing geometry blind -90
extrude "Extrude5" cut of existing geometry blind -15
sketch "Sketch4" plane through (0, 0, 0) normal (-1, 0, 0) x axis (0, 0, 1)
  line L1 (-103.5, 17.5) -> (-103.5, 12.5)
  line L2 (-97.5, 17.5) -> (-103.5, 17.5)
  line L3 (-97.5, 12.5) -> (-97.5, 17.5)
  line L4 (-103.5, 12.5) -> (-97.5, 12.5)
  line L5 (-57.5, 12.5) -> (-57.5, 17.5)
  line L6 (-62.5, 12.5) -> (-57.5, 12.5)
  line L7 (-62.5, 17.5) -> (-62.5, 12.5)
  line L8 (-57.5, 17.5) -> (-62.5, 17.5)
  line L9 (-22.5, 12.5) -> (-16.5, 12.5)
  line L10 (-22.5, 17.5) -> (-22.5, 12.5)
  line L11 (-16.5, 17.5) -> (-22.5, 17.5)
  line L12 (-16.5, 12.5) -> (-16.5, 17.5)
  line L13 (0, 0) -> (-120, 0)
  line L14 (0, 60) -> (0, 0)
  line L15 (-120, 60) -> (0, 60)
  line L16 (-120, 0) -> (-120, 60)
  line L17 (-115, 30) -> (-120, 30)
  line L18 (-115, 35) -> (-115, 30)
  line L19 (-120, 35) -> (-115, 35)
  line L20 (-120, 30) -> (-120, 35)
  line L21 (-115, 30) -> (-120, 30)
  line L22 (-115, 25) -> (-115, 30)
  line L23 (-120, 25) -> (-115, 25)
  line L24 (-120, 30) -> (-120, 25)
  point P18 (-120, 30)
  point P21 (-120, 35)
  point P19 (-115, 30)
  horizontal L17
  vertical L18
  horizontal L19
  vertical L20
  midpoint L16 P18
  horizontal L21
  vertical L22
  horizontal L23
  vertical L24
  dimension "d25" distance P18 P21 = 5
  dimension "d26" distance P18 P19 = 5
extrude "Extrude6" cut sketch "Sketch4" profile of L16 L17 L18 L19 L20 L21 L22 L23 L24 against normal blind 13
sketch "Sketch5" plane through (0, 0, 0) normal (-1, 0, 0) x axis (0, 0, 1)
  line L1 (-120, 25) -> (-115, 25)
  line L2 (-120, 0) -> (-120, 25)
  line L3 (0, 0) -> (-120, 0)
  line L4 (0, 60) -> (0, 0)
  line L5 (-120, 60) -> (0, 60)
  line L6 (-120, 35) -> (-120, 60)
  line L7 (-115, 35) -> (-120, 35)
  line L8 (-115, 25) -> (-115, 35)
  line L9 (-103.5, 17.5) -> (-103.5, 12.5)
  line L10 (-97.5, 17.5) -> (-103.5, 17.5)
  line L11 (-97.5, 12.5) -> (-97.5, 17.5)
  line L12 (-103.5, 12.5) -> (-97.5, 12.5)
  line L13 (-57.5, 12.5) -> (-57.5, 17.5)
  line L14 (-62.5, 12.5) -> (-57.5, 12.5)
  line L15 (-62.5, 17.5) -> (-62.5, 12.5)
  line L16 (-57.5, 17.5) -> (-62.5, 17.5)
  line L17 (-22.5, 12.5) -> (-16.5, 12.5)
  line L18 (-22.5, 17.5) -> (-22.5, 12.5)
  line L19 (-16.5, 17.5) -> (-22.5, 17.5)
  line L20 (-16.5, 12.5) -> (-16.5, 17.5)
  line L21 (-115, 47.5) -> (-120, 47.5)
  line L22 (-115, 52.5) -> (-115, 47.5)
  line L23 (-120, 52.5) -> (-115, 52.5)
  line L24 (-120, 47.5) -> (-120, 52.5)
  point P22 (-120, 47.5)
  point P25 (-120, 52.5)
  point P23 (-115, 47.5)
  horizontal L21
  vertical L22
  horizontal L23
  vertical L24
  midpoint L6 P22
  dimension "d29" distance P22 P25 = 5
  dimension "d30" distance P22 P23 = 5
extrude "Extrude7" cut sketch "Sketch5" profile of L6 L21 L22 L23 L24 against normal blind 14 named "d31_1"
sketch "Sketch6" plane through (0, 0, 0) normal (-1, 0, 0) x axis (0, 0, 1)
  line L1 (-22.5, 12.5) -> (-16.5, 12.5)
  line L2 (-22.5, 17.5) -> (-22.5, 12.5)
  line L3 (-16.5, 17.5) -> (-22.5, 17.5)
  line L4 (-16.5, 12.5) -> (-16.5, 17.5)
  line L5 (-57.5, 12.5) -> (-57.5, 17.5)
  line L6 (-62.5, 12.5) -> (-57.5, 12.5)
  line L7 (-62.5, 17.5) -> (-62.5, 12.5)
  line L8 (-57.5, 17.5) -> (-62.5, 17.5)
  line L9 (-103.5, 17.5) -> (-103.5, 12.5)
  line L10 (-97.5, 17.5) -> (-103.5, 17.5)
  line L11 (-97.5, 12.5) -> (-97.5, 17.5)
  line L12 (-103.5, 12.5) -> (-97.5, 12.5)
  line L13 (-115, 52.5) -> (-120, 52.5)
  line L14 (-115, 47.5) -> (-115, 52.5)
  line L15 (-120, 47.5) -> (-115, 47.5)
  line L16 (-120, 35) -> (-120, 47.5)
  line L17 (-115, 35) -> (-120, 35)
  line L18 (-115, 25) -> (-115, 35)
  line L19 (-120, 25) -> (-115, 25)
  line L20 (-120, 0) -> (-120, 25)
  line L21 (0, 0) -> (-120, 0)
  line L22 (0, 60) -> (0, 0)
  line L23 (-120, 60) -> (0, 60)
  line L24 (-120, 52.5) -> (-120, 60)
  line L25 (-115, 12.5) -> (-120, 12.5)
  line L26 (-115, 7.5) -> (-115, 12.5)
  line L27 (-120, 7.5) -> (-115, 7.5)
  line L28 (-120, 12.5) -> (-120, 7.5)
  point P26 (-120, 12.5)
  point P29 (-120, 7.5)
  point P27 (-115, 12.5)
  horizontal L25
  vertical L26
  horizontal L27
  vertical L28
  midpoint L20 P26
  dimension "d33_1" distance P26 P29 = 5
  dimension "d34_1" distance P26 P27 = 5
extrude "Extrude8" cut sketch "Sketch6" profile of L20 L25 L26 L27 L28 against normal blind 9 named "d35_1"
extrude "Extrude9" add of existing geometry blind 5
extrude "Extrude10" add of existing geometry blind 5 named "d39_1"
extrude "Extrude11" cut of existing geometry blind -35 named "d41_1"
sketch "Sketch7" plane through (0, 0, 0) normal (-1, 0, 0) x axis (0, 0, 1)
  line L1 (-120, 0) -> (-120, 25)
  line L2 (0, 0) -> (-120, 0)
  line L3 (0, 60) -> (0, 0)
  line L4 (-120, 60) -> (0, 60)
  line L5 (-120, 35) -> (-120, 60)
  line L6 (-115, 35) -> (-120, 35)
  line L7 (-115, 25) -> (-115, 35)
  line L8 (-120, 25) -> (-115, 25)
  line L9 (-103.5, 17.5) -> (-103.5, 12.5)
  line L10 (-97.5, 17.5) -> (-103.5, 17.5)
  line L11 (-97.5, 12.5) -> (-97.5, 17.5)
  line L12 (-103.5, 12.5) -> (-97.5, 12.5)
  line L13 (-57.5, 12.5) -> (-57.5, 17.5)
  line L14 (-62.5, 12.5) -> (-57.5, 12.5)
  line L15 (-62.5, 17.5) -> (-62.5, 12.5)
  line L16 (-57.5, 17.5) -> (-62.5, 17.5)
  line L17 (-22.5, 12.5) -> (-16.5, 12.5)
  line L18 (-22.5, 17.5) -> (-22.5, 12.5)
  line L19 (-16.5, 17.5) -> (-22.5, 17.5)
  line L20 (-16.5, 12.5) -> (-16.5, 17.5)
  line L21 (0, 35) -> (-5, 35)
  line L22 (0, 25) -> (0, 35)
  line L23 (-5, 25) -> (0, 25)
  line L24 (-5, 35) -> (-5, 25)
  point P24 (0, 25)
  horizontal L21
  vertical L22
  horizontal L23
  vertical L24
  coincident L3 P24
extrude "Extrude12" cut sketch "Sketch7" profile of L3 L21 L22 L23 L24 against normal blind 35 named "d43_1"
sketch "Sketch8" plane through (0, 0, 0) normal (0, 1, 0) x axis (1, 0, 0)
  line L1 (150, 0) -> (25, 0)
  line L2 (150, 5) -> (150, 0)
  line L3 (25, 5) -> (150, 5)
  line L4 (25, 0) -> (25, 5)
  point P2 (25, 0)
  point P3 (150, 0)
  point P5 (25, 5)
  horizontal L1
  vertical L2
  horizontal L3
  vertical L4
  dimension "d45_1" distance P2 P3 = 125
  dimension "d46_1" distance P2 P5 = 5
extrude "Extrude13" new body sketch "Sketch8" along normal blind 60 named "d47_1"
sketch "Sketch9" plane through (25, 0, 0) normal (-1, 0, 0) x axis (0, 0, 1)
  line L1 (0, 0) -> (-5, 0)
  line L2 (0, 60) -> (0, 0)
  line L3 (-5, 60) -> (0, 60)
  line L4 (-5, 0) -> (-5, 60)
  line L5 (0, 34.7875) -> (-5, 34.7875)
  line L6 (0, 25) -> (0, 34.7875)
  line L7 (-5, 25) -> (0, 25)
  line L8 (-5, 34.7875) -> (-5, 25)
  point P8 (0, 25)
  point P6 (-5, 34.7875)
  horizontal L5
  vertical L6
  horizontal L7
  vertical L8
  coincident L2 P8
  coincident L4 P6
extrude "Extrude14" add sketch "Sketch9" profile of L2 L4 L5 L6 L7 L8 along normal blind 5 named "d49_1"
extrude "Extrude15" cut of existing geometry blind -5 named "d51_1"
sketch "Sketch10" plane through (145, 0, 0) normal (1, 0, 0) x axis (0, 0, -1)
  line L1 (5, 0) -> (0, 0)
  line L2 (5, 60) -> (5, 0)
  line L3 (0, 60) -> (5, 60)
  line L4 (0, 0) -> (0, 60)
  line L5 (0, 35) -> (0, 60)
  line L6 (5, 35) -> (0, 35)
  line L7 (5, 25) -> (5, 35)
  line L8 (0, 25) -> (5, 25)
  line L9 (0, 35) -> (0, 25)
  point P5 (0, 60)
  point P6 (0, 60)
  point P7 (0, 35)
  point P10 (0, 25)
  point P8 (5, 35)
  coincident P5 P6
  perpendicular L3 L5
  horizontal L6
  vertical L7
  horizontal L8
  vertical L9
  dimension "d57_1" distance P6 P7 = 25
  dimension "d58_1" distance P7 P10 = 10
  dimension "d59_1" distance P7 P8 = 5
extrude "Extrude18" add sketch "Sketch10" profile of L2 L4 L6 L7 L8 L9 along normal blind 5 named "d60_1"
extrude "Extrude16" cut of existing geometry blind -0.212 named "d53_1"
extrude "Extrude17" add of existing geometry blind 0.424 (= "( 0.212 * 2 ) * 1 mm") named "d55_1"
sketch "Sketch11" plane through (0, 0, 0) normal (-1, 0, 0) x axis (0, 0, 1)
  line L1 (0, 35) -> (-5, 35)
  line L2 (0, 60) -> (0, 35)
  line L3 (-120, 60) -> (0, 60)
  line L4 (-120, 35) -> (-120, 60)
  line L5 (-115, 35) -> (-120, 35)
  line L6 (-115, 25) -> (-115, 35)
  line L7 (-120, 25) -> (-115, 25)
  line L8 (-120, 0) -> (-120, 25)
  line L9 (0, 0) -> (-120, 0)
  line L10 (0, 25) -> (0, 0)
  line L11 (-5, 25) -> (0, 25)
  line L12 (-5, 35) -> (-5, 25)
  line L13 (-103.5, 17.5) -> (-103.5, 12.5)
  line L14 (-97.5, 17.5) -> (-103.5, 17.5)
  line L15 (-97.5, 12.5) -> (-97.5, 17.5)
  line L16 (-103.5, 12.5) -> (-97.5, 12.5)
  line L17 (-57.5, 12.5) -> (-57.5, 17.5)
  line L18 (-62.5, 12.5) -> (-57.5, 12.5)
  line L19 (-62.5, 17.5) -> (-62.5, 12.5)
  line L20 (-57.5, 17.5) -> (-62.5, 17.5)
  line L21 (-22.5, 12.5) -> (-16.5, 12.5)
  line L22 (-22.5, 17.5) -> (-22.5, 12.5)
  line L23 (-16.5, 17.5) -> (-22.5, 17.5)
  line L24 (-16.5, 12.5) -> (-16.5, 17.5)
  circle C1 centre (-60, 30) radius 4.5
  dimension "d62_1" diameter C1 = 9
extrude "Extrude19" cut sketch "Sketch11" profile of C1 against normal blind 35 named "d63_1"
sketch "Sketch12" plane through (0, 0, 0) normal (-1, 0, 0) x axis (0, 0, 1)
  line L1 (0, 35) -> (-5, 35)
  line L2 (0, 60) -> (0, 35)
  line L3 (-120, 60) -> (0, 60)
  line L4 (-120, 35) -> (-120, 60)
  line L5 (-115, 35) -> (-120, 35)
  line L6 (-115, 25) -> (-115, 35)
  line L7 (-120, 25) -> (-115, 25)
  line L8 (-120, 0) -> (-120, 25)
  line L9 (0, 0) -> (-120, 0)
  line L10 (0, 25) -> (0, 0)
  line L11 (-5, 25) -> (0, 25)
  line L12 (-5, 35) -> (-5, 25)
  line L13 (-103.5, 17.5) -> (-103.5, 12.5)
  line L14 (-97.5, 17.5) -> (-103.5, 17.5)
  line L15 (-97.5, 12.5) -> (-97.5, 17.5)
  line L16 (-103.5, 12.5) -> (-97.5, 12.5)
  line L17 (-57.5, 12.5) -> (-57.5, 17.5)
  line L18 (-62.5, 12.5) -> (-57.5, 12.5)
  line L19 (-62.5, 17.5) -> (-62.5, 12.5)
  line L20 (-57.5, 17.5) -> (-62.5, 17.5)
  line L21 (-22.5, 12.5) -> (-16.5, 12.5)
  line L22 (-22.5, 17.5) -> (-22.5, 12.5)
  line L23 (-16.5, 17.5) -> (-22.5, 17.5)
  line L24 (-16.5, 12.5) -> (-16.5, 17.5)
  circle C1 centre (-60, 30) radius 4.5
sketch "Sketch13" plane through (0, 0, 0) normal (0, 0, 1) x axis (1, 0, 0)
  line L1 (20, 25) -> (20, 34.9995)
  line L2 (25, 25) -> (20, 25)
  line L3 (25, 0) -> (25, 25)
  line L4 (145, 0) -> (25, 0)
  line L5 (145, 25) -> (145, 0)
  line L6 (150, 25) -> (145, 25)
  line L7 (150, 35) -> (150, 25)
  line L8 (145, 35) -> (150, 35)
  line L9 (145, 60) -> (145, 35)
  line L10 (25, 60) -> (145, 60)
  line L11 (25, 34.9995) -> (25, 60)
  line L12 (20, 34.9995) -> (25, 34.9995)
extrude "Extrude20" add of existing geometry blind 0.13 named "d65_1"
extrude "Extrude21" add of existing geometry blind 0.13 named "d67_1"
extrude "Extrude22" add of existing geometry blind 0.2 named "d69_1"
extrude "Extrude23" add of existing geometry blind 0.13 named "d71_1"
extrude "Extrude24" add of existing geometry blind 0.13 named "d73_1"
extrude "Extrude25" add of existing geometry blind 0.13 named "d75_1"
extrude "Extrude26" add of existing geometry blind 0.13 named "d77_1"
extrude "Extrude27" add of existing geometry blind 0.2 named "d79_1"
sketch "Sketch14" plane through (0, 0, 0) normal (-1, 0, 0) x axis (0, 0, 1)
  line L1 (0, 35) -> (-5, 35)
  line L2 (0, 60) -> (0, 35)
  line L3 (-120, 60) -> (0, 60)
  line L4 (-120, 35) -> (-120, 60)
  line L5 (-115, 35) -> (-120, 35)
  line L6 (-115, 25) -> (-115, 35)
  line L7 (-120, 25) -> (-115, 25)
  line L8 (-120, 0) -> (-120, 25)
  line L9 (0, 0) -> (-120, 0)
  line L10 (0, 25) -> (0, 0)
  line L11 (-5, 25) -> (0, 25)
  line L12 (-5, 35) -> (-5, 25)
  line L13 (-103.5, 17.5) -> (-103.5, 12.5)
  line L14 (-97.5, 17.5) -> (-103.5, 17.5)
  line L15 (-97.5, 12.5) -> (-97.5, 17.5)
  line L16 (-103.5, 12.5) -> (-97.5, 12.5)
  line L17 (-57.5, 12.5) -> (-57.5, 17.5)
  line L18 (-62.5, 12.5) -> (-57.5, 12.5)
  line L19 (-62.5, 17.5) -> (-62.5, 12.5)
  line L20 (-57.5, 17.5) -> (-62.5, 17.5)
  line L21 (-22.5, 12.5) -> (-16.5, 12.5)
  line L22 (-22.5, 17.5) -> (-22.5, 12.5)
  line L23 (-16.5, 17.5) -> (-22.5, 17.5)
  line L24 (-16.5, 12.5) -> (-16.5, 17.5)
  circle C1 centre (-60, 30) radius 4.5
  circle C2 centre (-60, 30) radius 4.5
  concentric C1 C2
extrude "Extrude28" add sketch "Sketch14" profile of C1 C2 against normal blind 5 named "d81_1"
sketch "Sketch15" plane through (0, 0, 0) normal (-1, 0, 0) x axis (0, 0, 1)
  line L1 (0, 35) -> (-5, 35)
  line L2 (0, 60) -> (0, 35)
  line L3 (-120, 60) -> (0, 60)
  line L4 (-120, 35) -> (-120, 60)
  line L5 (-115, 35) -> (-120, 35)
  line L6 (-115, 25) -> (-115, 35)
  line L7 (-120, 25) -> (-115, 25)
  line L8 (-120, 0) -> (-120, 25)
  line L9 (0, 0) -> (-120, 0)
  line L10 (0, 25) -> (0, 0)
  line L11 (-5, 25) -> (0, 25)
  line L12 (-5, 35) -> (-5, 25)
  line L13 (-103.5, 17.5) -> (-103.5, 12.5)
  line L14 (-97.5, 17.5) -> (-103.5, 17.5)
  line L15 (-97.5, 12.5) -> (-97.5, 17.5)
  line L16 (-103.5, 12.5) -> (-97.5, 12.5)
  line L17 (-57.5, 12.5) -> (-57.5, 17.5)
  line L18 (-62.5, 12.5) -> (-57.5, 12.5)
  line L19 (-62.5, 17.5) -> (-62.5, 12.5)
  line L20 (-57.5, 17.5) -> (-62.5, 17.5)
  line L21 (-22.5, 12.5) -> (-16.5, 12.5)
  line L22 (-22.5, 17.5) -> (-22.5, 12.5)
  line L23 (-16.5, 17.5) -> (-22.5, 17.5)
  line L24 (-16.5, 12.5) -> (-16.5, 17.5)
  circle C1 centre (-60, 30) radius 6
  dimension "d83_1" diameter C1 = 12
extrude "Extrude29" cut sketch "Sketch15" profile of C1 against normal blind 5 named "d84_1"
extrude "Extrude30" cut of existing geometry blind -0.35 named "d86_1"
extrude "Extrude31" cut of existing geometry blind -0.35 named "d88_1"
extrude "Extrude32" cut of existing geometry blind -0.35 named "d90_1"
extrude "Extrude33" cut of existing geometry blind -0.35 named "d92_1"
extrude "Extrude34" cut of existing geometry blind -0.73 named "d94_1"
extrude "Extrude35" cut of existing geometry blind -0.73 named "d96_1"
extrude "Extrude36" cut of existing geometry blind -0.73 named "d98_1"
extrude "Extrude37" cut of existing geometry blind -0.73 named "d100_1"
extrude "Extrude38" cut of existing geometry blind -0.73 named "d102_1"
extrude "Extrude39" cut of existing geometry blind -0.73 named "d104_1"
extrude "Extrude40" cut of existing geometry blind -1.35 named "d106_1"
extrude "Extrude41" cut of existing geometry blind -1.35 named "d108_1"
extrude "Extrude42" add of existing geometry blind 0.5 named "d110_1"
extrude "Extrude43" add of existing geometry blind 0.5 named "d112_1"
sketch "Sketch16" plane through (0, 0, 0) normal (-1, 0, 0) x axis (0, 0, 1)
  line L1 (-56.65, 18.23) -> (-63.35, 18.23)
  line L2 (-56.65, 11.77) -> (-56.65, 18.23)
  line L3 (-63.35, 11.77) -> (-56.65, 11.77)
  line L4 (-63.35, 18.23) -> (-63.35, 11.77)
  line L5 (-22.85, 18.23) -> (-22.85, 11.77)
  line L6 (-16.15, 18.23) -> (-22.85, 18.23)
  line L7 (-16.15, 11.77) -> (-16.15, 18.23)
  line L8 (-22.85, 11.77) -> (-16.15, 11.77)
  line L9 (-103.85, 18.23) -> (-103.85, 11.77)
  line L10 (-97.15, 18.23) -> (-103.85, 18.23)
  line L11 (-97.15, 11.77) -> (-97.15, 18.23)
  line L12 (-103.85, 11.77) -> (-97.15, 11.77)
  line L13 (0, 35) -> (-5, 35)
  line L14 (0, 60) -> (0, 35)
  line L15 (-120, 60) -> (0, 60)
  line L16 (-120, 35) -> (-120, 60)
  line L17 (-115, 35) -> (-120, 35)
  line L18 (-115, 25) -> (-115, 35)
  line L19 (-120, 25) -> (-115, 25)
  line L20 (-120, 0) -> (-120, 25)
  line L21 (0, 0) -> (-120, 0)
  line L22 (0, 25) -> (0, 0)
  line L23 (-5, 25) -> (0, 25)
  line L24 (-5, 35) -> (-5, 25)
  circle C1 centre (-60, 30) radius 6
sketch "Sketch17" plane through (0, 0, 0) normal (0, 0, 1) x axis (1, 0, 0)
  line L1 (25, 24.87) -> (19.67, 24.87)
  line L2 (25, 0) -> (25, 24.87)
  line L3 (145, 0) -> (25, 0)
  line L4 (145, 24.87) -> (145, 0)
  line L5 (150.33, 24.87) -> (145, 24.87)
  line L6 (150.33, 35.13) -> (150.33, 24.87)
  line L7 (145, 35.13) -> (150.33, 35.13)
  line L8 (145, 60) -> (145, 35.13)
  line L9 (25, 60) -> (145, 60)
  line L10 (25, 35.1295) -> (25, 60)
  line L11 (19.67, 35.1295) -> (25, 35.1295)
  line L12 (19.67, 24.87) -> (19.67, 35.1295)
work_plane "WorkPlane1" AlongDistance -60 named "d114_1"
split "Split1"
move "Move1"
extrude "Extrude44" add of existing geometry blind 80 named "d115_1"
extrude "Extrude45" add of existing geometry blind 0.175 named "d117_1"
extrude "Extrude46" add of existing geometry blind 0.175 named "d119_1"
